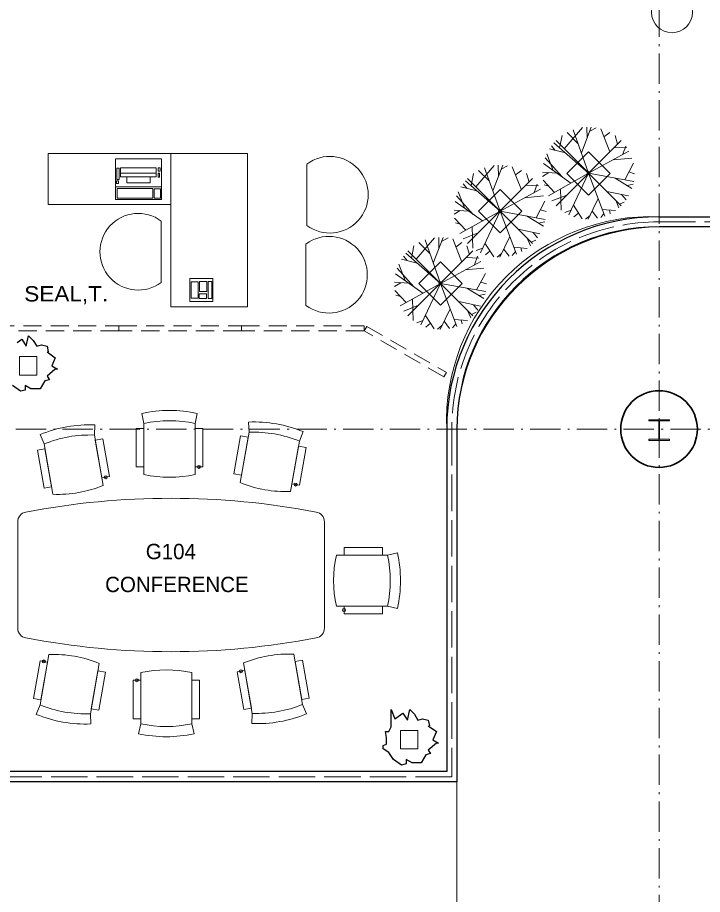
# Model space of a CAD drawing. Extents: x -118748 to -117136, y -118748 to -117596.
# Drawn here: x -118260.7 to -118046.3, y -118330.4 to -118056 of the extents above; entities that cross this region are included whole.
import ezdxf
from ezdxf.enums import TextEntityAlignment as Align

# ---------------------------------------------------------------- set-up
doc = ezdxf.new("R2010")
doc.units = 0
doc.header["$LTSCALE"] = 1.9
doc.header["$PDMODE"] = 32
doc.header["$PDSIZE"] = 0.95
for name, pattern in [('DOT_DASHED', [7.7, 5, -1.2, 0.3, -1.2]), ('LONG_DASHED', [7.5, 6, -1.5]), ('MEDIUM_DASHED', [4.5, 3, -1.5])]:
    doc.linetypes.add(name, pattern=pattern)
for name, color, linetype, lineweight in [('10', 7, 'DOT_DASHED', 13), ('12', 7, 'Continuous', 13), ('15', 7, 'Continuous', 13), ('16', 7, 'Continuous', 13), ('17', 7, 'Continuous', 25), ('20', 7, 'MEDIUM_DASHED', 13), ('23', 7, 'Continuous', 25), ('30', 7, 'Continuous', 13), ('5', 7, 'Continuous', 13), ('6', 7, 'Continuous', 13), ('60', 7, 'LONG_DASHED', 13), ('9', 7, 'Continuous', 35)]:
    doc.layers.add(name, color=color, linetype=linetype, lineweight=lineweight)
doc.layers.add('53', color=7, linetype='Continuous')

msp = doc.modelspace()

# ---------------------------------------------------------------- linework, layer by layer
at = {"layer": '10'}
for p, q in [((-118059.921, -117628.339), (-118059.921, -118698.41)), ((-118641.571, -118184.81), (-117285.521, -118184.81))]:
    msp.add_line(p, q, dxfattribs=at)
at = {"layer": '12'}
msp.add_lwpolyline([(-118063.104, -118188.362), (-118056.688, -118188.362), (-118056.688, -118187.966), (-118059.772, -118187.966), (-118059.772, -118182.262), (-118056.688, -118182.262), (-118056.688, -118181.866), (-118063.104, -118181.866), (-118063.104, -118182.262), (-118060.02, -118182.262), (-118060.02, -118187.966), (-118063.104, -118187.966)], close=True, dxfattribs=at)
at = {"layer": '12', "lineweight": 35}
msp.add_circle((-118059.921, -118184.81), 12, dxfattribs=at)
at = {"layer": '15'}
for p, q in [((-118170.125, -118101.88), (-118170.125, -118121.08)), ((-118215.687, -118138.921), (-118215.687, -118119.721)), ((-118170.406, -118126.911), (-118170.406, -118146.111)), ((-118221.115, -118183.043), (-118221.791, -118179.915)), ((-118205.115, -118183.043), (-118204.439, -118179.915)), ((-118188.233, -118185.8), (-118188.355, -118182.602)), ((-118236.62, -118186.688), (-118236.497, -118183.49)), ((-118223.515, -118196.643), (-118223.515, -118184.643)), ((-118221.115, -118184.643), (-118223.515, -118184.643)), ((-118221.115, -118199.043), (-118221.115, -118183.043)), ((-118221.115, -118196.643), (-118221.115, -118184.643)), ((-118205.115, -118199.043), (-118205.115, -118183.043)), ((-118205.115, -118196.643), (-118205.115, -118184.643)), ((-118202.715, -118184.643), (-118205.115, -118184.643)), ((-118202.715, -118196.643), (-118202.715, -118184.643)), ((-118172.476, -118188.578), (-118171.267, -118185.615)), ((-118252.377, -118189.466), (-118253.586, -118186.504)), ((-118233.842, -118202.445), (-118236.62, -118186.688)), ((-118233.979, -118187.847), (-118236.342, -118188.264)), ((-118234.259, -118200.082), (-118236.342, -118188.264)), ((-118231.895, -118199.665), (-118233.979, -118187.847)), ((-118192.958, -118198.776), (-118190.874, -118186.959)), ((-118191.011, -118201.557), (-118188.233, -118185.8)), ((-118188.511, -118187.375), (-118190.874, -118186.959)), ((-118190.594, -118199.193), (-118188.511, -118187.375)), ((-118252.099, -118191.042), (-118254.463, -118191.459)), ((-118249.599, -118205.223), (-118252.377, -118189.466)), ((-118250.015, -118202.86), (-118252.099, -118191.042)), ((-118175.254, -118204.335), (-118172.476, -118188.578)), ((-118174.837, -118201.971), (-118172.754, -118190.154)), ((-118170.39, -118190.57), (-118172.754, -118190.154)), ((-118172.474, -118202.388), (-118170.39, -118190.57)), ((-118252.379, -118203.277), (-118254.463, -118191.459)), ((-118223.515, -118196.643), (-118221.115, -118196.643)), ((-118205.115, -118196.643), (-118202.715, -118196.643)), ((-118192.958, -118198.776), (-118190.594, -118199.193)), ((-118234.259, -118200.082), (-118231.895, -118199.665)), ((-118174.837, -118201.971), (-118172.474, -118202.388)), ((-118252.379, -118203.277), (-118250.015, -118202.86)), ((-118260.633, -118213.904), (-118260.633, -118247.038)), ((-118164.633, -118213.904), (-118164.633, -118247.038)), ((-118158.491, -118221.843), (-118146.491, -118221.843)), ((-118158.491, -118221.843), (-118158.491, -118224.243)), ((-118146.491, -118224.243), (-118146.491, -118221.843)), ((-118144.891, -118224.243), (-118141.763, -118223.567)), ((-118160.891, -118224.243), (-118144.891, -118224.243)), ((-118158.491, -118224.243), (-118146.491, -118224.243)), ((-118160.891, -118240.243), (-118144.891, -118240.243)), ((-118158.491, -118240.243), (-118146.491, -118240.243)), ((-118158.491, -118240.243), (-118158.491, -118242.643)), ((-118146.491, -118242.643), (-118146.491, -118240.243)), ((-118144.891, -118240.243), (-118141.763, -118240.92)), ((-118158.491, -118242.643), (-118146.491, -118242.643)), ((-118250.851, -118255.363), (-118253.629, -118271.12)), ((-118174.239, -118255.23), (-118171.46, -118270.987)), ((-118253.631, -118257.31), (-118255.715, -118269.127)), ((-118251.268, -118257.726), (-118253.631, -118257.31)), ((-118251.268, -118257.726), (-118253.351, -118269.544)), ((-118235.094, -118258.141), (-118237.872, -118273.898)), ((-118189.996, -118258.009), (-118187.217, -118273.766)), ((-118171.458, -118257.177), (-118173.822, -118257.594)), ((-118173.822, -118257.594), (-118171.738, -118269.412)), ((-118171.458, -118257.177), (-118169.375, -118268.995)), ((-118235.511, -118260.505), (-118237.595, -118272.322)), ((-118233.147, -118260.921), (-118235.511, -118260.505)), ((-118233.147, -118260.921), (-118235.231, -118272.739)), ((-118222.124, -118261.033), (-118222.124, -118277.033)), ((-118206.124, -118261.033), (-118206.124, -118277.033)), ((-118189.579, -118260.372), (-118191.942, -118260.789)), ((-118191.942, -118260.789), (-118189.859, -118272.607)), ((-118189.579, -118260.372), (-118187.495, -118272.19)), ((-118224.524, -118263.433), (-118224.524, -118275.433)), ((-118222.124, -118263.433), (-118224.524, -118263.433)), ((-118222.124, -118263.433), (-118222.124, -118275.433)), ((-118206.124, -118263.433), (-118206.124, -118275.433)), ((-118203.724, -118263.433), (-118206.124, -118263.433)), ((-118203.724, -118263.433), (-118203.724, -118275.433)), ((-118255.715, -118269.127), (-118253.351, -118269.544)), ((-118171.738, -118269.412), (-118169.375, -118268.995)), ((-118253.629, -118271.12), (-118254.838, -118274.083)), ((-118237.595, -118272.322), (-118235.231, -118272.739)), ((-118189.859, -118272.607), (-118187.495, -118272.19)), ((-118171.46, -118270.987), (-118170.251, -118273.95)), ((-118237.872, -118273.898), (-118237.75, -118277.096)), ((-118224.524, -118275.433), (-118222.124, -118275.433)), ((-118206.124, -118275.433), (-118203.724, -118275.433)), ((-118187.217, -118273.766), (-118187.34, -118276.963)), ((-118222.124, -118277.033), (-118222.8, -118280.16)), ((-118206.124, -118277.033), (-118205.448, -118280.16))]:
    msp.add_line(p, q, dxfattribs=at)
for points in [[(-118212.687, -118114.556), (-118212.687, -118098.556), (-118251.087, -118098.556), (-118251.087, -118114.556)], [(-118188.687, -118146.556), (-118188.687, -118098.556), (-118212.687, -118098.556), (-118212.687, -118146.556)]]:
    msp.add_lwpolyline(points, close=True, dxfattribs=at)
for centre, radius, start, end in [((-118162.925, -118111.48), 12, 233.13011, 126.8699), ((-118222.887, -118129.321), 12, 53.1301, 306.8699), ((-118163.206, -118136.511), 12, 233.13011, 126.8699), ((-118213.115, -118220.051), 41.063, 77.80217, 102.19783), ((-118213.115, -118220.051), 37.863, 77.80217, 102.19783), ((-118213.115, -118220.051), 37.863, 77.80217, 102.19783), ((-118186.781, -118223.635), 41.063, 67.80217, 92.19783), ((-118238.072, -118224.523), 41.063, 87.80217, 112.19783), ((-118238.072, -118224.523), 37.863, 87.80217, 112.19783), ((-118238.072, -118224.523), 37.863, 87.80217, 112.19783), ((-118186.781, -118223.635), 37.863, 67.80217, 92.19783), ((-118186.781, -118223.635), 37.863, 67.80217, 92.19783), ((-118213.115, -118162.035), 37.863, 257.80217, 282.19783), ((-118176.706, -118166.5), 37.863, 247.80217, 272.19783), ((-118248.147, -118167.388), 37.863, 267.80217, 292.19782), ((-118212.633, -118448.871), 242.4, 79.20527, 100.79473), ((-118257.433, -118213.904), 3.2, 100.79473, 180), ((-118167.833, -118213.904), 3.2, 0, 79.20527), ((-118181.899, -118232.243), 41.063, 347.80217, 12.19783), ((-118123.883, -118232.243), 37.863, 167.80217, 192.19783), ((-118181.899, -118232.243), 37.863, 347.80217, 12.19783), ((-118181.899, -118232.243), 37.863, 347.80217, 12.19783), ((-118257.433, -118247.038), 3.2, 180, 259.20527), ((-118167.833, -118247.038), 3.2, 280.79473, 0), ((-118212.633, -118012.071), 242.4, 259.20527, 280.79473), ((-118249.399, -118293.198), 37.863, 67.80217, 92.19783), ((-118175.691, -118293.065), 37.863, 87.80217, 112.19782), ((-118214.124, -118298.041), 37.863, 77.80217, 102.19783), ((-118239.324, -118236.063), 37.863, 247.80217, 272.19783), ((-118239.324, -118236.063), 37.863, 247.80217, 272.19783), ((-118185.765, -118235.93), 37.863, 267.80217, 292.19783), ((-118185.765, -118235.93), 37.863, 267.80217, 292.19783), ((-118239.324, -118236.063), 41.063, 247.80217, 272.19783), ((-118185.765, -118235.93), 41.063, 267.80217, 292.19783), ((-118214.124, -118240.024), 37.863, 257.80217, 282.19783), ((-118214.124, -118240.024), 37.863, 257.80217, 282.19783), ((-118214.124, -118240.024), 41.063, 257.80217, 282.19783)]:
    msp.add_arc(centre, radius, start, end, dxfattribs=at)
for p in [(-118203.915, -118196.643), (-118233.077, -118199.873), (-118173.656, -118202.18), (-118158.491, -118241.443), (-118252.449, -118257.518), (-118190.761, -118260.581), (-118223.324, -118263.433)]:
    msp.add_point(p, dxfattribs=at)
at = {"layer": '16'}
msp.add_line((-118230.068, -118109.006), (-118215.668, -118109.006), dxfattribs=at)
for points in [[(-118230.068, -118113.006), (-118230.068, -118100.206), (-118215.668, -118100.206), (-118215.668, -118113.006)], [(-118229.61, -118106.724), (-118229.61, -118103.187), (-118228.903, -118103.187), (-118228.903, -118106.724)], [(-118228.404, -118104.685), (-118228.404, -118103.085), (-118217.295, -118103.085), (-118217.295, -118104.685)], [(-118216.67, -118103.104), (-118216.67, -118104.102), (-118216.088, -118104.102), (-118216.088, -118103.104)], [(-118228.404, -118105.891), (-118228.404, -118104.685), (-118217.295, -118104.685), (-118217.295, -118105.891)], [(-118226.49, -118107.764), (-118226.49, -118105.891), (-118219.167, -118105.891), (-118219.167, -118107.764)], [(-118216.67, -118104.685), (-118216.67, -118105.933), (-118216.254, -118105.933), (-118216.254, -118104.685)], [(-118229.693, -118107.972), (-118229.693, -118107.14), (-118229.028, -118107.14), (-118229.028, -118107.972)], [(-118229.527, -118109.553), (-118229.527, -118112.549), (-118218.335, -118112.549), (-118218.335, -118109.553)], [(-118217.919, -118109.636), (-118217.919, -118112.59), (-118215.922, -118112.59), (-118215.922, -118109.636)], [(-118199.545, -118137.661), (-118199.545, -118144.861), (-118206.745, -118144.861), (-118206.745, -118137.661)], [(-118204.164, -118143.826), (-118204.164, -118138.708), (-118206.369, -118138.708), (-118206.369, -118143.826)], [(-118201.418, -118141.787), (-118201.418, -118138.667), (-118203.706, -118138.667), (-118203.706, -118141.787)], [(-118201.001, -118138.667), (-118201.001, -118143.909), (-118199.92, -118143.909), (-118199.92, -118138.667)], [(-118201.501, -118143.909), (-118201.501, -118142.453), (-118203.789, -118142.453), (-118203.789, -118143.909)]]:
    msp.add_lwpolyline(points, close=True, dxfattribs=at)
at = {"layer": '17'}
for points in [[(-118260.82, -118157.765), (-118259.372, -118156.679), (-118257.924, -118158.851), (-118257.2, -118155.593), (-118255.751, -118157.041), (-118254.665, -118158.851), (-118253.217, -118158.489), (-118251.407, -118158.851), (-118251.045, -118160.662)], [(-118251.407, -118160.662), (-118248.873, -118162.472), (-118249.959, -118165.006), (-118248.149, -118166.092), (-118248.873, -118166.092), (-118251.407, -118168.264), (-118250.683, -118169.351), (-118252.131, -118169.713), (-118253.579, -118172.247), (-118256.475, -118172.247), (-118258.286, -118171.161), (-118258.286, -118172.609), (-118259.734, -118172.971), (-118262.268, -118171.161)], [(-118132.141, -118277.667), (-118129.606, -118279.477), (-118130.692, -118282.012), (-118128.882, -118283.098), (-118129.606, -118283.098), (-118132.141, -118285.27), (-118131.416, -118286.356), (-118132.865, -118286.718), (-118134.313, -118289.252), (-118137.209, -118289.252), (-118139.019, -118288.166), (-118139.019, -118289.614), (-118140.467, -118289.976), (-118143.002, -118288.166), (-118144.45, -118285.994), (-118146.26, -118284.908), (-118146.26, -118283.822), (-118145.174, -118283.46), (-118145.174, -118281.287), (-118145.536, -118279.477), (-118144.45, -118279.477), (-118143.726, -118278.029), (-118143.726, -118272.599), (-118142.64, -118275.495), (-118141.554, -118274.771), (-118140.105, -118273.685), (-118138.657, -118275.857), (-118137.933, -118272.599), (-118136.485, -118274.047), (-118135.399, -118275.857), (-118133.951, -118275.495), (-118132.141, -118275.857), (-118131.778, -118277.667)]]:
    msp.add_lwpolyline(points, dxfattribs=at)
at = {"layer": '17', "lineweight": 13}
for points in [[(-118254.665, -118162.11), (-118254.665, -118167.902), (-118260.096, -118167.902), (-118260.096, -118162.11)], [(-118135.399, -118279.115), (-118135.399, -118284.908), (-118140.829, -118284.908), (-118140.829, -118279.115)]]:
    msp.add_lwpolyline(points, close=True, dxfattribs=at)
at = {"layer": '20'}
for points in [[(-118229.002, -118152.479), (-118229.002, -118154.079), (-118267.402, -118154.079), (-118267.402, -118152.479)], [(-118190.602, -118152.479), (-118190.602, -118154.079), (-118229.002, -118154.079), (-118229.002, -118152.479)], [(-118152.202, -118152.479), (-118152.202, -118154.079), (-118190.602, -118154.079), (-118190.602, -118152.479)], [(-118126.46, -118167.093), (-118127.26, -118168.479), (-118152.202, -118154.079), (-118151.402, -118152.693)]]:
    msp.add_lwpolyline(points, close=True, dxfattribs=at)
at = {"layer": '23'}
for p, q in [((-118059.921, -118118.36), (-118018.321, -118118.36)), ((-118016.721, -118121.56), (-118059.921, -118121.56)), ((-118126.371, -118184.81), (-118126.371, -118292.01)), ((-118123.171, -118184.81), (-118123.171, -118295.21)), ((-118126.371, -118292.01), (-118463.121, -118292.01)), ((-118123.171, -118295.21), (-118463.121, -118295.21))]:
    msp.add_line(p, q, dxfattribs=at)
for radius in [66.45, 63.25]:
    msp.add_arc((-118059.921, -118184.81), radius, 90, 180, dxfattribs=at)
at = {"layer": '30'}
for p, q in [((-118089.555, -118097.147), (-118083.817, -118090.447)), ((-118085.29, -118095.401), (-118088.7, -118091.996)), ((-118081.974, -118104.728), (-118086.798, -118091.16)), ((-118084.222, -118098.405), (-118081.119, -118090.354)), ((-118082.438, -118093.776), (-118082.529, -118090.339)), ((-118081.598, -118091.594), (-118079.594, -118090.526)), ((-118075.306, -118098.06), (-118078.141, -118090.848)), ((-118077.141, -118093.392), (-118075.272, -118091.983)), ((-118071.792, -118114.911), (-118092.156, -118094.546)), ((-118092.156, -118114.911), (-118071.792, -118094.546)), ((-118091.041, -118096.805), (-118090.266, -118092.955)), ((-118072.897, -118095.651), (-118073.663, -118092.969)), ((-118089.209, -118098.406), (-118094.211, -118097.138)), ((-118092.393, -118097.599), (-118093.565, -118096.183)), ((-118081.974, -118104.728), (-118092.817, -118095.253)), ((-118081.974, -118104.728), (-118069.321, -118097.854)), ((-118073.911, -118096.665), (-118069.945, -118096.812)), ((-118071.33, -118098.945), (-118070.325, -118096.263)), ((-118090.35, -118105.786), (-118095.568, -118099.977)), ((-118093.045, -118103.877), (-118095.042, -118098.679)), ((-118074.248, -118100.531), (-118068.376, -118099.99)), ((-118117.252, -118109.017), (-118111.514, -118102.317)), ((-118109.671, -118116.598), (-118114.495, -118103.03)), ((-118111.919, -118110.275), (-118108.816, -118102.224)), ((-118110.135, -118105.646), (-118110.225, -118102.209)), ((-118109.294, -118103.464), (-118107.291, -118102.396)), ((-118103.003, -118109.93), (-118105.838, -118102.718)), ((-118087.48, -118107.817), (-118096.061, -118101.742)), ((-118070.649, -118106.803), (-118067.918, -118101.602)), ((-118118.738, -118108.676), (-118117.963, -118104.826)), ((-118112.987, -118107.271), (-118116.397, -118103.866)), ((-118104.838, -118105.262), (-118102.968, -118103.853)), ((-118100.594, -118107.521), (-118101.36, -118104.839)), ((-118091.861, -118104.715), (-118096.37, -118104.39)), ((-118094.408, -118104.532), (-118096.34, -118105.72)), ((-118081.974, -118104.728), (-118094.533, -118111.773)), ((-118081.974, -118104.728), (-118088.1, -118117.76)), ((-118081.974, -118104.728), (-118076.859, -118118.189)), ((-118081.974, -118104.728), (-118067.81, -118107.324)), ((-118069.341, -118104.311), (-118067.575, -118104.904)), ((-118120.09, -118109.469), (-118121.262, -118108.054)), ((-118109.671, -118116.598), (-118120.514, -118107.123)), ((-118099.489, -118126.781), (-118119.853, -118106.416)), ((-118119.853, -118126.781), (-118099.489, -118106.416)), ((-118101.608, -118108.535), (-118097.642, -118108.682)), ((-118099.027, -118110.815), (-118098.022, -118108.133)), ((-118092.671, -118110.729), (-118096.204, -118106.937)), ((-118094.441, -118108.829), (-118095.891, -118108.428)), ((-118073.683, -118106.248), (-118068.381, -118109.482)), ((-118069.921, -118108.542), (-118067.982, -118108.132)), ((-118120.741, -118115.748), (-118122.739, -118110.549)), ((-118116.906, -118110.276), (-118121.908, -118109.008)), ((-118109.671, -118116.598), (-118097.018, -118109.724)), ((-118088.82, -118111.574), (-118093.473, -118113.396)), ((-118090.707, -118109.627), (-118090.527, -118116.313)), ((-118076.269, -118110.433), (-118069.47, -118111.87)), ((-118071.654, -118111.408), (-118070.239, -118113.074)), ((-118115.177, -118119.687), (-118123.758, -118113.612)), ((-118118.047, -118117.656), (-118123.265, -118111.847)), ((-118101.945, -118112.401), (-118096.073, -118111.861)), ((-118098.346, -118118.673), (-118095.614, -118113.472)), ((-118078.961, -118112.659), (-118082.075, -118119.128)), ((-118073.48, -118113.222), (-118072.475, -118115.551)), ((-118072.263, -118114.439), (-118070.777, -118113.783)), ((-118119.558, -118116.586), (-118124.067, -118116.26)), ((-118122.104, -118116.402), (-118124.037, -118117.59)), ((-118109.671, -118116.598), (-118122.23, -118123.644)), ((-118109.671, -118116.598), (-118115.796, -118129.63)), ((-118109.671, -118116.598), (-118104.556, -118130.059)), ((-118109.671, -118116.598), (-118095.507, -118119.194)), ((-118097.037, -118116.182), (-118095.272, -118116.774)), ((-118087.432, -118116.34), (-118089.413, -118117.058)), ((-118086.699, -118114.781), (-118083.953, -118118.992)), ((-118080.847, -118116.577), (-118079.169, -118118.852)), ((-118077.672, -118116.051), (-118073.533, -118116.395)), ((-118075.459, -118116.235), (-118075.168, -118117.418)), ((-118120.368, -118122.599), (-118123.9, -118118.807)), ((-118101.38, -118118.118), (-118096.078, -118121.352)), ((-118085.114, -118117.211), (-118086.528, -118118.389)), ((-118081.51, -118117.954), (-118082.912, -118119.098)), ((-118077.162, -118117.392), (-118078.177, -118118.619)), ((-118122.138, -118120.699), (-118123.588, -118120.298)), ((-118118.404, -118121.498), (-118118.224, -118128.183)), ((-118103.966, -118122.303), (-118097.167, -118123.74)), ((-118097.618, -118120.412), (-118095.679, -118120.002)), ((-118135.905, -118131.627), (-118130.167, -118124.926)), ((-118130.572, -118132.885), (-118127.469, -118124.833)), ((-118128.788, -118128.255), (-118128.879, -118124.819)), ((-118127.948, -118126.074), (-118125.944, -118125.006)), ((-118121.656, -118132.54), (-118124.491, -118125.327)), ((-118116.517, -118123.444), (-118121.17, -118125.267)), ((-118106.658, -118124.529), (-118109.772, -118130.998)), ((-118101.177, -118125.092), (-118100.172, -118127.421)), ((-118099.351, -118123.278), (-118097.936, -118124.944)), ((-118137.391, -118131.285), (-118136.616, -118127.435)), ((-118131.64, -118129.881), (-118135.05, -118126.475)), ((-118128.324, -118139.208), (-118133.148, -118125.64)), ((-118123.491, -118127.872), (-118121.622, -118126.463)), ((-118119.247, -118130.131), (-118120.013, -118127.449)), ((-118114.396, -118126.651), (-118111.65, -118130.862)), ((-118105.369, -118127.921), (-118101.23, -118128.265)), ((-118099.96, -118126.309), (-118098.474, -118125.653)), ((-118138.743, -118132.079), (-118139.915, -118130.663)), ((-118128.324, -118139.208), (-118139.167, -118129.733)), ((-118118.142, -118149.39), (-118138.506, -118129.026)), ((-118138.506, -118149.39), (-118118.142, -118129.026)), ((-118117.68, -118133.425), (-118116.675, -118130.743)), ((-118115.129, -118128.21), (-118117.109, -118128.928)), ((-118112.811, -118129.081), (-118114.225, -118130.259)), ((-118109.207, -118129.824), (-118110.609, -118130.968)), ((-118108.544, -118128.448), (-118106.866, -118130.723)), ((-118104.859, -118129.262), (-118105.874, -118130.489)), ((-118103.156, -118128.105), (-118102.865, -118129.288)), ((-118139.395, -118138.357), (-118141.392, -118133.159)), ((-118135.559, -118132.886), (-118140.561, -118131.618)), ((-118128.324, -118139.208), (-118115.671, -118132.334)), ((-118120.261, -118131.145), (-118116.295, -118131.292)), ((-118133.83, -118142.297), (-118142.411, -118136.221)), ((-118136.7, -118140.265), (-118141.918, -118134.457)), ((-118120.598, -118135.011), (-118114.726, -118134.47)), ((-118116.999, -118141.283), (-118114.268, -118136.082)), ((-118138.211, -118139.195), (-118142.72, -118138.87)), ((-118140.758, -118139.011), (-118142.69, -118140.2)), ((-118115.691, -118138.791), (-118113.925, -118139.383)), ((-118139.021, -118145.209), (-118142.554, -118141.417)), ((-118128.324, -118139.208), (-118140.883, -118146.253)), ((-118128.324, -118139.208), (-118134.45, -118152.24)), ((-118128.324, -118139.208), (-118123.209, -118152.669)), ((-118128.324, -118139.208), (-118114.16, -118141.804)), ((-118120.033, -118140.727), (-118114.731, -118143.962)), ((-118140.791, -118143.308), (-118142.241, -118142.907)), ((-118137.057, -118144.107), (-118136.877, -118150.792)), ((-118116.271, -118143.022), (-118114.332, -118142.611)), ((-118135.17, -118146.054), (-118139.823, -118147.876)), ((-118125.311, -118147.139), (-118128.425, -118153.608)), ((-118122.619, -118144.913), (-118115.82, -118146.35)), ((-118118.004, -118145.888), (-118116.589, -118147.554)), ((-118133.049, -118149.261), (-118130.303, -118153.471)), ((-118119.83, -118147.702), (-118118.825, -118150.031)), ((-118118.613, -118148.919), (-118117.127, -118148.263)), ((-118133.782, -118150.819), (-118135.763, -118151.538)), ((-118131.464, -118151.691), (-118132.878, -118152.869)), ((-118127.86, -118152.434), (-118129.262, -118153.577)), ((-118127.197, -118151.057), (-118125.519, -118153.332)), ((-118123.512, -118151.872), (-118124.527, -118153.098)), ((-118124.022, -118150.53), (-118119.883, -118150.875)), ((-118121.809, -118150.714), (-118121.518, -118151.898))]:
    msp.add_line(p, q, dxfattribs=at)
for points in [[(-118081.971, -118111.581), (-118088.759, -118104.793), (-118081.971, -118098.005), (-118075.183, -118104.793)], [(-118109.668, -118123.451), (-118116.456, -118116.663), (-118109.668, -118109.875), (-118102.879, -118116.663)], [(-118128.321, -118146.061), (-118135.109, -118139.273), (-118128.321, -118132.484), (-118121.533, -118139.273)]]:
    msp.add_lwpolyline(points, close=True, dxfattribs=at)
msp.add_circle((-118055.846, -118054.383), 6.4, dxfattribs=at)
for p in [(-118081.974, -118104.728), (-118109.671, -118116.598), (-118128.324, -118139.208)]:
    msp.add_point(p, dxfattribs=at)
at = {"layer": '5'}
msp.add_line((-118059.921, -118121.56), (-117906.321, -118121.56), dxfattribs=at)
for points in [[(-118496.721, -117964.01), (-118098.321, -117964.01), (-117984.721, -117964.01), (-117984.721, -118118.36), (-118059.921, -118118.36)], [(-118126.371, -118184.81), (-118126.371, -118292.01), (-118463.121, -118292.01), (-118496.721, -118292.01), (-118496.721, -118180.01), (-118496.721, -117964.01)], [(-118123.174, -118415.21), (-118123.175, -118343.21), (-118272.721, -118343.21), (-118496.721, -118343.21), (-118496.721, -118333.61), (-118496.721, -118301.61), (-118496.721, -118295.21), (-118463.121, -118295.21), (-118123.171, -118295.21), (-118123.171, -118184.81)]]:
    msp.add_lwpolyline(points, dxfattribs=at)
for radius in [66.45, 63.25]:
    msp.add_arc((-118059.921, -118184.81), radius, 90, 180, dxfattribs=at)
at = {"layer": '6'}
for p, q in [((-118059.921, -118121.56), (-117906.321, -118121.56)), ((-118123.175, -118415.21), (-118123.171, -118184.81))]:
    msp.add_line(p, q, dxfattribs=at)
for points in [[(-118126.371, -118184.81), (-118126.371, -118292.01), (-118496.721, -118292.01), (-118496.721, -117964.01)], [(-118496.721, -117964.01), (-117984.721, -117964.01), (-117984.721, -118118.36), (-118059.921, -118118.36)]]:
    msp.add_lwpolyline(points, dxfattribs=at)
msp.add_lwpolyline([(-118496.721, -118343.21), (-118123.171, -118343.21), (-118123.171, -118295.21), (-118496.721, -118295.21)], close=True, dxfattribs=at)
for centre, radius, start, end in [((-118062.35, -118182.38), 64.067, 87.82672, 182.17328), ((-118059.208, -118185.523), 63.967, 90.63868, 179.36132)]:
    msp.add_arc(centre, radius, start, end, dxfattribs=at)
at = {"layer": '60'}
for p, q in [((-118059.921, -118119.96), (-117983.121, -118119.96)), ((-118124.771, -118184.81), (-118124.771, -118293.61)), ((-118124.771, -118293.61), (-118498.321, -118293.61))]:
    msp.add_line(p, q, dxfattribs=at)
msp.add_arc((-118059.921, -118184.81), 64.85, 90, 180, dxfattribs=at)

# ---------------------------------------------------------------- texts
at = {"layer": '53', "width": 1.1}
msp.add_text('SEAL,T.', height=4.8, dxfattribs=at).set_placement((-118258.582, -118144.882))
at = {"layer": '53'}
msp.add_text('CONFERENCE', height=4.8, dxfattribs=at).set_placement((-118233.265, -118235.83))
at = {"layer": '9'}
msp.add_text('G104', height=4.8, dxfattribs=at).set_placement((-118212.693, -118225.525), align=Align.CENTER)

doc.saveas('drawing.dxf')
